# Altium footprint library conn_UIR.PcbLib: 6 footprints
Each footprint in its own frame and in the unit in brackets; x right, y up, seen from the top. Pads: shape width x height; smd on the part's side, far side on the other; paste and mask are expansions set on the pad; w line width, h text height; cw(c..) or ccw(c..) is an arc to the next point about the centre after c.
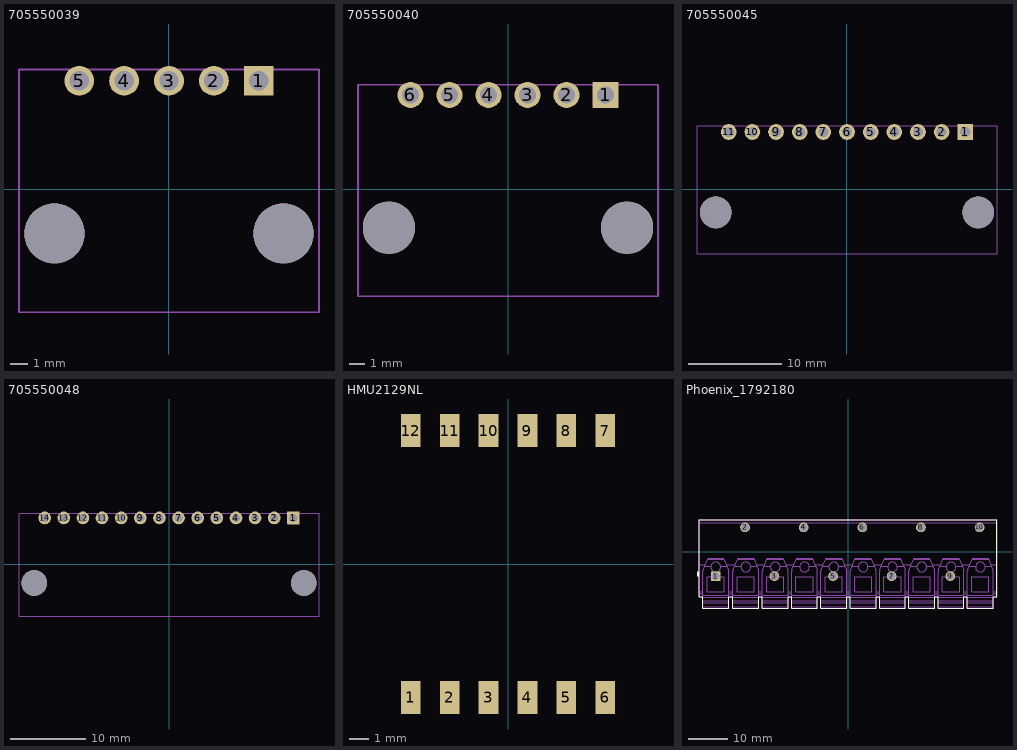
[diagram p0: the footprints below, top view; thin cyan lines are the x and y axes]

## 705550039 [mm]
height 1.1
pads (7):
  rrect6% 1.69x1.69 hole 1.09 paste-1000 mask+0: 1(5.09,6.145)
  round 1.69 hole 1.09 paste-1000 mask+0: 2(2.55,6.145) 3(0.01,6.145) 4(-2.53,6.145) 5(-5.07,6.145)
  round 3.4 hole 3.4 unplated paste-1000 mask+0: ""(-6.47,-2.495) ""(6.49,-2.495)
Mechanical 5:
  lines w0.1: -8.48,-6.95 8.5,-6.95 8.5,6.795 ; -8.48,-6.945 -8.48,6.795 ; -8.48,6.79 8.5,6.79
  text ".Designator" at -3.8,0.022 h0.5
3D body "705550039.stp": height 7.11, standoff -3.17, extent -8.255,-6.915 8.255,6.674

## 705550040 [mm]
height 1.1
pads (8):
  rrect6% 1.69x1.69 hole 1.09 paste-1000 mask+0: 1(6.35,6.145)
  round 1.69 hole 1.09 paste-1000 mask+0: 2(3.81,6.145) 3(1.27,6.145) 4(-1.27,6.145) 5(-3.81,6.145) 6(-6.35,6.145)
  round 3.4 hole 3.4 unplated paste-1000 mask+0: ""(-7.75,-2.495) ""(7.75,-2.495)
Mechanical 5:
  lines w0.1: -9.76,-6.945 -9.76,6.795 9.76,6.795 9.76,-6.945 -9.76,-6.945
  text ".Designator" at 0,0.022 h0.5
3D body "705550040.stp": height 7.12, standoff -3.17, extent -9.525,-6.789 9.525,6.8

## 705550045 [mm]
height 1.1
pads (13):
  rrect6% 1.69x1.69 hole 1.09 paste-1000 mask+0: 1(12.71,6.145)
  round 1.69 hole 1.09 paste-1000 mask+0: 2(10.17,6.145) 3(7.63,6.145) 4(5.09,6.145) 5(2.55,6.145) 6(0.01,6.145) 7(-2.53,6.145) 8(-5.07,6.145) 9(-7.61,6.145) 10(-10.15,6.145) 11(-12.69,6.145)
  round 3.4 hole 3.4 unplated paste-1000 mask+0: ""(-14.09,-2.495) ""(14.11,-2.495)
Mechanical 5:
  lines w0.1: -16.1,-6.945 16.12,-6.945 16.12,6.795 -16.1,6.795 -16.1,-6.945
  text ".Designator" at -3.8,0.022 h0.5
3D body "705550045.stp": height 7.11, standoff -3.17, extent -15.875,-6.789 15.875,6.8

## 705550048 [mm]
height 1.1
pads (16):
  rrect6% 1.69x1.69 hole 1.09 paste-1000 mask+0: 1(16.51,6.145)
  round 1.69 hole 1.09 paste-1000 mask+0: 2(13.97,6.145) 3(11.43,6.145) 4(8.89,6.145) 5(6.35,6.145) 6(3.81,6.145) 7(1.27,6.145) 8(-1.27,6.145) 9(-3.81,6.145) 10(-6.35,6.145) 11(-8.89,6.145) 12(-11.43,6.145) 13(-13.97,6.145) 14(-16.51,6.145)
  round 3.4 hole 3.4 unplated paste-1000 mask+0: ""(-17.91,-2.495) ""(17.91,-2.495)
Mechanical 5:
  lines w0.1: -19.92,-6.945 -19.92,6.795 19.92,6.795 19.92,-6.945 -19.92,-6.945
  text ".Designator" at 0,0.022 h0.5
3D body "705550048.stp": height 7.11, standoff -3.17, extent -19.685,-6.794 19.685,6.795

## HMU2129NL [mm]
pads (12):
  rect 1.02x1.715 smd: 1(-5.025,-6.893) 2(-3.015,-6.893) 3(-1.005,-6.893) 4(1.005,-6.893) 5(3.015,-6.893) 6(5.025,-6.893) 7(5.025,6.893) 8(3.015,6.893) 9(1.005,6.893) 10(-1.005,6.893) 11(-3.015,6.893) 12(-5.025,6.893)

## Phoenix_1792180 [mm] "Receptacle, 7.5mm, 10x1, TH"
height 24.1
pads (10):
  rect 2.5x2.5 hole 2: 1(-33.9,-6.25)
  round 2.5 hole 2: 2(-26.4,6.25) 3(-18.9,-6.25) 4(-11.4,6.25) 5(-3.9,-6.25) 6(3.6,6.25) 7(11.1,-6.25) 8(18.6,6.25) 9(26.1,-6.25) 10(33.6,6.25)
Top Overlay:
  rectangle: -38.7,-6.3 -38.1,-5
  lines w0.2: -37.2,-11.6 -37.2,-12.554 -37.2,-13.05 -37.2,-14.004 -37.2,-14.5 -30.6,-14.5 -30.6,-14.004 -30.6,-13.05 -30.6,-12.554 -30.6,-11.6 ; -37.2,-11.55 -38.15,-11.55 -38.15,-10.75 -38.15,-10.217 -38.15,-3.35 -38.15,7.461 -38.15,8.25 38.05,8.25 38.05,7.461 38.05,-3.35 38.05,-10.217 38.05,-10.75 38.05,-11.55 37.55,-11.55 37.1,-11.55 ; -30.6,-11.55 -30.45,-11.55 -30.15,-11.55 -29.5,-11.55 ; -29.5,-11.6 -29.5,-12.554 -29.5,-13.05 -29.5,-14.004 -29.5,-14.5 -22.9,-14.5 -22.9,-14.004 -22.9,-13.05 -22.9,-12.554 -22.9,-11.6 ; -22.9,-11.55 -22.45,-11.55 -22,-11.55 ; -22,-11.6 -22,-12.554 -22,-13.05 -22,-14.004 -22,-14.5 -15.4,-14.5 -15.4,-14.004 -15.4,-13.05 -15.4,-12.554 -15.4,-11.6 ; -15.4,-11.55 -14.95,-11.55 -14.5,-11.55 ; -14.5,-11.6 -14.5,-12.554 -14.5,-13.05 -14.5,-14.004 -14.5,-14.5 -7.9,-14.5 -7.9,-14.004 -7.9,-13.05 -7.9,-12.554 -7.9,-11.6 ; -7.9,-11.55 -7.45,-11.55 -7,-11.55 ; -7,-11.6 -7,-12.554 -7,-13.05 -7,-14.004 -7,-14.5 -0.4,-14.5 -0.4,-14.004 -0.4,-13.05 -0.4,-12.554 -0.4,-11.6 ; -0.4,-11.55 0.05,-11.55 0.5,-11.55 ; 0.5,-11.6 0.5,-12.554 0.5,-13.05 0.5,-14.004 0.5,-14.5 7.1,-14.5 7.1,-14.004 7.1,-13.05 7.1,-12.554 7.1,-11.6 ; 7.1,-11.55 7.55,-11.55 8,-11.55 ; 8,-11.6 8,-12.554 8,-13.05 8,-14.004 8,-14.5 14.6,-14.5 14.6,-14.004 14.6,-13.05 14.6,-12.554 14.6,-11.6 ; 14.6,-11.55 15.05,-11.55 15.5,-11.55 ; 15.5,-11.6 15.5,-12.554 15.5,-13.05 15.5,-14.004 15.5,-14.5 22.1,-14.5 22.1,-14.004 22.1,-13.05 22.1,-12.554 22.1,-11.6 ; 22.1,-11.55 22.55,-11.55 23,-11.55 ; 23,-11.6 23,-12.554 23,-13.05 23,-14.004 23,-14.5 29.6,-14.5 29.6,-14.004 29.6,-13.05 29.6,-12.554 29.6,-11.6 ; 29.6,-11.55 30.05,-11.55 30.5,-11.55 ; 30.5,-11.6 30.5,-12.554 30.5,-13.05 30.5,-14.004 30.5,-14.5 37.1,-14.5 37.1,-14.004 37.1,-13.05 37.1,-12.554 37.1,-11.6
Mechanical 5:
  drawing of 521 lines, arcs and shapes, not listed
  text ".Designator" at -3.7,0.9 h1.85
3D body "pxc_1792180_03_PLH-5-10-7-5-ZF_3D.stp": height 24.1, standoff -3.6, extent -38.15,-14.5 38.05,8.25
